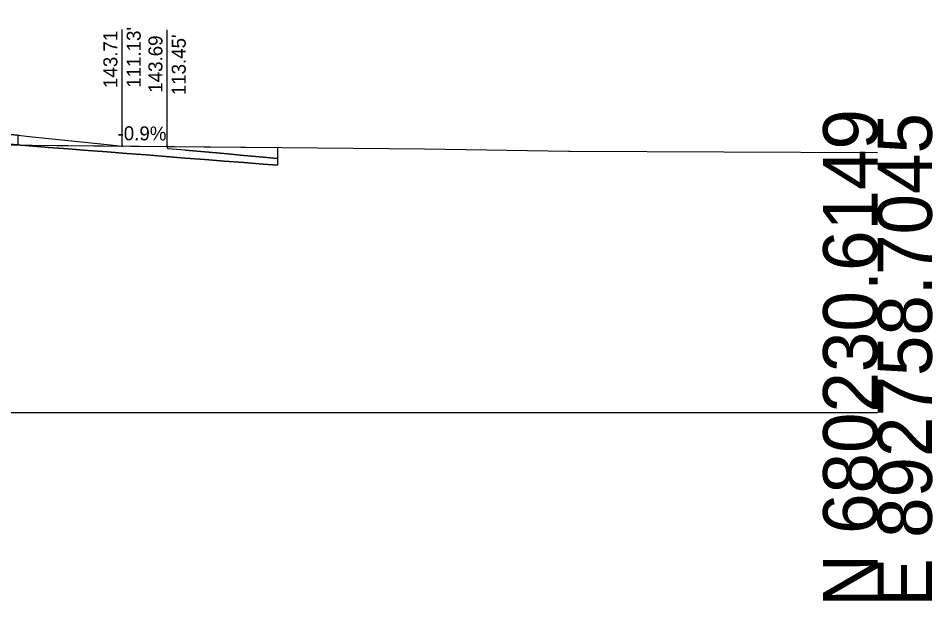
# Model space of a CAD drawing. Extents: x -26 to 4403, y -13 to 9578.
# Drawn here: x 355.79 to 402.84, y 1490.31 to 1520.28 of the extents above; entities that cross this region are included whole.
import ezdxf

# ---------------------------------------------------------------- set-up
doc = ezdxf.new("R2010")
doc.units = 0
for name, color, linetype in [('DTM_P_FINISHED_GRADE', 7, 'Continuous'), ('DTM_X_GROUND', 7, 'Continuous'), ('X_PROFILES_1', 7, 'Continuous'), ('XS_CELL', 7, 'Continuous'), ('XS_M_SHAPES_EARTHWORK', 7, 'Continuous'), ('XS_P_DR_GRAVEL', 7, 'Continuous'), ('XS_P_GROUND', 7, 'Continuous'), ('XS_P_TX_CLEARZONE', 7, 'Continuous'), ('XS_P_TX_FS_BS', 7, 'Continuous')]:
    doc.layers.add(name, color=color, linetype=linetype)

msp = doc.modelspace()

# ---------------------------------------------------------------- linework, layer by layer
at = {"layer": 'DTM_P_FINISHED_GRADE'}
msp.add_lwpolyline([(355.348, 1514.295), (355.79, 1514.26)], dxfattribs=at)
at = {"layer": 'DTM_X_GROUND'}
msp.add_lwpolyline([(262.308, 1520.28), (267.608, 1519.607), (269.532, 1519.51), (276.336, 1518.635), (277.085, 1518.481), (289.466, 1516.992), (290.351, 1516.958), (298.112, 1516.358), (306.607, 1515.6), (308.072, 1515.483), (315.908, 1515.07), (328.844, 1514.348), (332.234, 1514.262), (338.414, 1514.095), (347.871, 1513.84), (348.208, 1513.842), (349.143, 1513.812), (376.688, 1513.569), (384.125, 1513.444), (384.178, 1513.434), (400, 1513.374)], dxfattribs=at)
at = {"layer": 'XS_CELL'}
msp.add_line((250, 1500), (400, 1500), dxfattribs=at)
at = {"layer": 'XS_M_SHAPES_EARTHWORK'}
msp.add_lwpolyline([(349.143, 1513.812), (355.887, 1513.753), (355.79, 1513.76), (355.348, 1513.795)], dxfattribs=at)
for points in [[(355.887, 1513.753), (369.129, 1513.636), (369.129, 1512.718), (368.397, 1512.775), (367.393, 1512.853), (366.39, 1512.932), (365.386, 1513.01), (364.382, 1513.089), (363.378, 1513.167), (362.374, 1513.246), (361.371, 1513.324), (360.367, 1513.403), (359.363, 1513.481), (358.359, 1513.56), (357.355, 1513.638), (356.351, 1513.717)], [(363.445, 1513.686), (369.129, 1513.636), (369.129, 1513.07), (368.397, 1513.135), (367.393, 1513.225), (366.39, 1513.315), (365.386, 1513.404), (364.382, 1513.494), (363.484, 1513.568)]]:
    msp.add_lwpolyline(points, close=True, dxfattribs=at)
at = {"layer": 'XS_P_DR_GRAVEL'}
for points in [[(355.348, 1513.795), (355.79, 1513.76), (355.79, 1514.26), (355.348, 1514.295)], [(355.79, 1513.76), (356.351, 1513.717), (357.355, 1513.638), (358.359, 1513.56), (359.363, 1513.481), (360.367, 1513.403), (361.371, 1513.324), (362.374, 1513.246), (363.378, 1513.167), (364.382, 1513.089), (365.386, 1513.01), (366.39, 1512.932), (367.393, 1512.853), (368.397, 1512.775), (369.129, 1512.718)]]:
    msp.add_lwpolyline(points, dxfattribs=at)
at = {"layer": 'XS_P_GROUND'}
for points in [[(355.79, 1514.26), (356.351, 1514.202), (357.355, 1514.098), (358.359, 1513.994), (359.363, 1513.89), (360.367, 1513.786), (361.128, 1513.706)], [(364.382, 1513.494), (363.484, 1513.568), (363.445, 1513.686)], [(364.382, 1513.494), (365.386, 1513.404), (366.39, 1513.315), (367.393, 1513.225), (368.397, 1513.135), (369.129, 1513.07)]]:
    msp.add_lwpolyline(points, dxfattribs=at)
at = {"layer": 'XS_P_TX_CLEARZONE'}
for p, q in [((361.128, 1513.706), (361.128, 1519.706)), ((361.128, 1513.706), (361.128, 1519.706)), ((361.128, 1513.706), (361.128, 1519.706)), ((363.445, 1513.686), (363.445, 1519.686)), ((363.445, 1513.686), (363.445, 1519.686)), ((363.445, 1513.686), (363.445, 1519.686)), ((363.445, 1513.686), (363.445, 1519.686)), ((363.445, 1513.686), (363.445, 1519.686)), ((363.445, 1513.686), (363.445, 1519.686))]:
    msp.add_line(p, q, dxfattribs=at)

# ---------------------------------------------------------------- texts
at = {"layer": 'X_PROFILES_1'}
for p in [(361.089, 1513.646), (363.406, 1513.626)]:
    msp.add_text('X', height=0.12, dxfattribs=at).set_placement(p)
at = {"layer": 'XS_CELL'}
for s, p in [('N 680230.6149', (400, 1490)), ('E 892758.7045', (402.8, 1490))]:
    msp.add_text(s, height=2.8, rotation=90, dxfattribs=at).set_placement(p)
at = {"layer": 'XS_P_TX_CLEARZONE'}
for s, p in [("111.13'", (362.088, 1516.703)), ("111.13'", (362.088, 1516.703)), ("111.13'", (362.088, 1516.703)), ('143.71', (360.888, 1516.692)), ('143.71', (360.888, 1516.692)), ('143.71', (360.888, 1516.692)), ('143.69', (363.205, 1516.45)), ('143.69', (363.205, 1516.45)), ('143.69', (363.205, 1516.45)), ('143.69', (363.205, 1516.45)), ('143.69', (363.205, 1516.45)), ('143.69', (363.205, 1516.45)), ("113.45'", (364.405, 1516.32)), ("113.45'", (364.405, 1516.32)), ("113.45'", (364.405, 1516.32)), ("113.45'", (364.405, 1516.32)), ("113.45'", (364.405, 1516.32)), ("113.45'", (364.405, 1516.32))]:
    msp.add_text(s, height=0.72, rotation=90, dxfattribs=at).set_placement(p)
at = {"layer": 'XS_P_TX_FS_BS'}
msp.add_text('-0.9%', height=0.72, rotation=359.4933, dxfattribs=at).set_placement((360.893, 1514.009))
msp.add_text('-0.9%', height=0.72, rotation=359.4933, dxfattribs=at).set_placement((360.893, 1514.009))
msp.add_text('-0.9%', height=0.72, rotation=359.4933, dxfattribs=at).set_placement((360.893, 1514.009))

doc.saveas('drawing.dxf')
